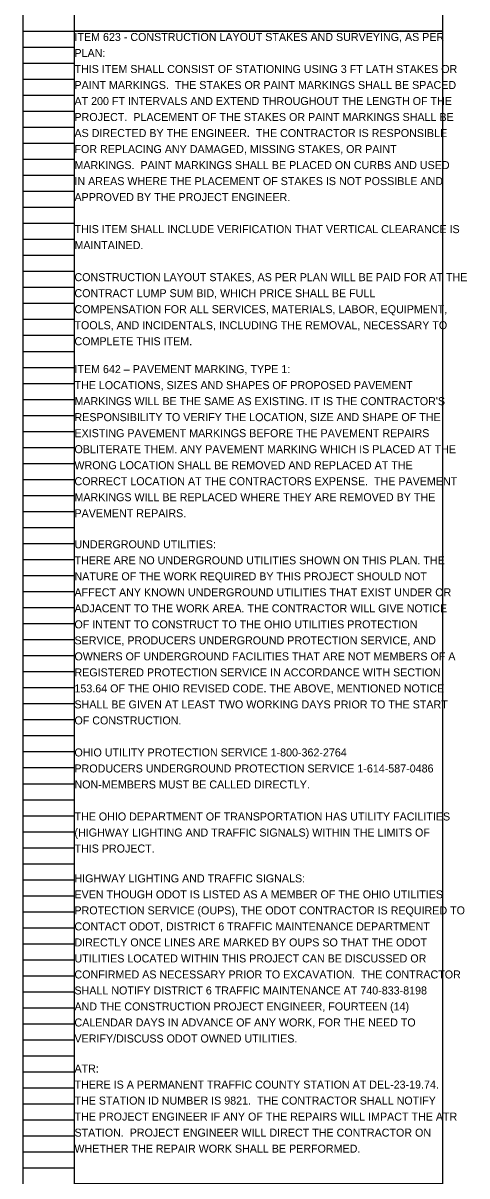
# Model space of a CAD drawing. Extents: x 16463 to 16495, y 5662 to 5823.
# Drawn here: x 16463.05 to 16470.82, y 5763.13 to 5783.29 of the extents above; entities that cross this region are included whole.
import ezdxf

# ---------------------------------------------------------------- set-up
doc = ezdxf.new("R2010")
doc.units = 0
for name, color, linetype in [('Default', 7, 'Continuous'), ('SC_Scratch1', 7, 'Continuous'), ('SH_Data', 7, 'Continuous')]:
    doc.layers.add(name, color=color, linetype=linetype)

msp = doc.modelspace()

# ---------------------------------------------------------------- linework, layer by layer
at = {"layer": 'SC_Scratch1'}
for points in [[(16463.949, 5803.312), (16470.389, 5803.312), (16470.389, 5783.152), (16463.949, 5783.152)], [(16463.949, 5783.152), (16470.389, 5783.152), (16470.389, 5762.992), (16463.949, 5762.992)]]:
    msp.add_lwpolyline(points, close=True, dxfattribs=at)
at = {"layer": 'SH_Data'}
for p, q in [((16463.049, 5783.152), (16463.049, 5803.312)), ((16463.949, 5783.152), (16463.949, 5803.312)), ((16463.049, 5762.992), (16463.049, 5783.152)), ((16463.049, 5783.152), (16463.949, 5783.152)), ((16463.049, 5783.152), (16463.949, 5783.152)), ((16463.949, 5762.992), (16463.949, 5783.152)), ((16463.049, 5782.872), (16463.949, 5782.872)), ((16463.049, 5782.592), (16463.949, 5782.592)), ((16463.049, 5782.312), (16463.949, 5782.312)), ((16463.049, 5782.032), (16463.949, 5782.032)), ((16463.049, 5781.752), (16463.949, 5781.752)), ((16463.049, 5781.472), (16463.949, 5781.472)), ((16463.049, 5781.192), (16463.949, 5781.192)), ((16463.049, 5780.912), (16463.949, 5780.912)), ((16463.049, 5780.632), (16463.949, 5780.632)), ((16463.049, 5780.352), (16463.949, 5780.352)), ((16463.049, 5780.072), (16463.949, 5780.072)), ((16463.049, 5779.792), (16463.949, 5779.792)), ((16463.049, 5779.512), (16463.949, 5779.512)), ((16463.049, 5779.232), (16463.949, 5779.232)), ((16463.049, 5778.952), (16463.949, 5778.952)), ((16463.049, 5778.672), (16463.949, 5778.672)), ((16463.049, 5778.392), (16463.949, 5778.392)), ((16463.049, 5778.112), (16463.949, 5778.112)), ((16463.049, 5777.832), (16463.949, 5777.832)), ((16463.049, 5777.552), (16463.949, 5777.552)), ((16463.049, 5777.272), (16463.949, 5777.272)), ((16463.049, 5776.992), (16463.949, 5776.992)), ((16463.049, 5776.712), (16463.949, 5776.712)), ((16463.049, 5776.432), (16463.949, 5776.432)), ((16463.049, 5776.152), (16463.949, 5776.152)), ((16463.049, 5775.872), (16463.949, 5775.872)), ((16463.049, 5775.592), (16463.949, 5775.592)), ((16463.049, 5775.312), (16463.949, 5775.312)), ((16463.049, 5775.032), (16463.949, 5775.032)), ((16463.049, 5774.752), (16463.949, 5774.752)), ((16463.049, 5774.472), (16463.949, 5774.472)), ((16463.049, 5774.192), (16463.949, 5774.192)), ((16463.049, 5773.912), (16463.949, 5773.912)), ((16463.049, 5773.632), (16463.949, 5773.632)), ((16463.049, 5773.352), (16463.949, 5773.352)), ((16463.049, 5773.072), (16463.949, 5773.072)), ((16463.049, 5772.792), (16463.949, 5772.792)), ((16463.049, 5772.512), (16463.949, 5772.512)), ((16463.049, 5772.232), (16463.949, 5772.232)), ((16463.049, 5771.952), (16463.949, 5771.952)), ((16463.049, 5771.672), (16463.949, 5771.672)), ((16463.049, 5771.392), (16463.949, 5771.392)), ((16463.049, 5771.112), (16463.949, 5771.112)), ((16463.049, 5770.832), (16463.949, 5770.832)), ((16463.049, 5770.552), (16463.949, 5770.552)), ((16463.049, 5770.272), (16463.949, 5770.272)), ((16463.049, 5769.992), (16463.949, 5769.992)), ((16463.049, 5769.712), (16463.949, 5769.712)), ((16463.049, 5769.432), (16463.949, 5769.432)), ((16463.049, 5769.152), (16463.949, 5769.152)), ((16463.049, 5768.872), (16463.949, 5768.872)), ((16463.049, 5768.592), (16463.949, 5768.592)), ((16463.049, 5768.312), (16463.949, 5768.312)), ((16463.049, 5768.032), (16463.949, 5768.032)), ((16463.049, 5767.752), (16463.949, 5767.752)), ((16463.049, 5767.472), (16463.949, 5767.472)), ((16463.049, 5767.192), (16463.949, 5767.192)), ((16463.049, 5766.912), (16463.949, 5766.912)), ((16463.049, 5766.632), (16463.949, 5766.632)), ((16463.049, 5766.352), (16463.949, 5766.352)), ((16463.049, 5766.072), (16463.949, 5766.072)), ((16463.049, 5765.792), (16463.949, 5765.792)), ((16463.049, 5765.512), (16463.949, 5765.512)), ((16463.049, 5765.232), (16463.949, 5765.232)), ((16463.049, 5764.952), (16463.949, 5764.952)), ((16463.049, 5764.672), (16463.949, 5764.672)), ((16463.049, 5764.392), (16463.949, 5764.392)), ((16463.049, 5764.112), (16463.949, 5764.112)), ((16463.049, 5763.832), (16463.949, 5763.832)), ((16463.049, 5763.552), (16463.949, 5763.552)), ((16463.049, 5763.272), (16463.949, 5763.272))]:
    msp.add_line(p, q, dxfattribs=at)

# ---------------------------------------------------------------- texts
at = {"layer": 'Default'}
for s, p in [('ITEM 623 - CONSTRUCTION LAYOUT STAKES AND SURVEYING, AS PER ', (16463.949, 5782.979)), ('PLAN:', (16463.949, 5782.699)), ('THIS ITEM SHALL CONSIST OF STATIONING USING 3 FT LATH STAKES OR ', (16463.949, 5782.419)), ('PAINT MARKINGS.  THE STAKES OR PAINT MARKINGS SHALL BE SPACED ', (16463.949, 5782.139)), ('AT 200 FT INTERVALS AND EXTEND THROUGHOUT THE LENGTH OF THE ', (16463.949, 5781.859)), ('PROJECT.  PLACEMENT OF THE STAKES OR PAINT MARKINGS SHALL BE ', (16463.949, 5781.579)), ('AS DIRECTED BY THE ENGINEER.  THE CONTRACTOR IS RESPONSIBLE ', (16463.949, 5781.299)), ('FOR REPLACING ANY DAMAGED, MISSING STAKES, OR PAINT ', (16463.949, 5781.019)), ('MARKINGS.  PAINT MARKINGS SHALL BE PLACED ON CURBS AND USED ', (16463.949, 5780.739)), ('IN AREAS WHERE THE PLACEMENT OF STAKES IS NOT POSSIBLE AND ', (16463.949, 5780.459)), ('APPROVED BY THE PROJECT ENGINEER.', (16463.949, 5780.179)), ('THIS ITEM SHALL INCLUDE VERIFICATION THAT VERTICAL CLEARANCE IS ', (16463.949, 5779.619)), ('MAINTAINED.', (16463.949, 5779.339)), ('CONSTRUCTION LAYOUT STAKES, AS PER PLAN WILL BE PAID FOR AT THE ', (16463.949, 5778.779)), ('CONTRACT LUMP SUM BID, WHICH PRICE SHALL BE FULL ', (16463.949, 5778.499)), ('COMPENSATION FOR ALL SERVICES, MATERIALS, LABOR, EQUIPMENT, ', (16463.949, 5778.219)), ('TOOLS, AND INCIDENTALS, INCLUDING THE REMOVAL, NECESSARY TO ', (16463.949, 5777.939)), ('COMPLETE THIS ITEM.', (16463.949, 5777.659)), ('ITEM 642 – PAVEMENT MARKING, TYPE 1:', (16463.949, 5777.171)), ('THE LOCATIONS, SIZES AND SHAPES OF PROPOSED PAVEMENT ', (16463.949, 5776.891)), ("MARKINGS WILL BE THE SAME AS EXISTING. IT IS THE CONTRACTOR'S ", (16463.949, 5776.611)), ('RESPONSIBILITY TO VERIFY THE LOCATION, SIZE AND SHAPE OF THE ', (16463.949, 5776.331)), ('EXISTING PAVEMENT MARKINGS BEFORE THE PAVEMENT REPAIRS ', (16463.949, 5776.051)), ('OBLITERATE THEM. ANY PAVEMENT MARKING WHICH IS PLACED AT THE ', (16463.949, 5775.771)), ('WRONG LOCATION SHALL BE REMOVED AND REPLACED AT THE ', (16463.949, 5775.491)), ('CORRECT LOCATION AT THE CONTRACTORS EXPENSE.  THE PAVEMENT ', (16463.949, 5775.211)), ('MARKINGS WILL BE REPLACED WHERE THEY ARE REMOVED BY THE ', (16463.949, 5774.931)), ('PAVEMENT REPAIRS.', (16463.949, 5774.651)), ('UNDERGROUND UTILITIES:', (16463.949, 5774.108)), ('THERE ARE NO UNDERGROUND UTILITIES SHOWN ON THIS PLAN. THE ', (16463.949, 5773.828)), ('NATURE OF THE WORK REQUIRED BY THIS PROJECT SHOULD NOT ', (16463.949, 5773.548)), ('AFFECT ANY KNOWN UNDERGROUND UTILITIES THAT EXIST UNDER OR ', (16463.949, 5773.268)), ('ADJACENT TO THE WORK AREA. THE CONTRACTOR WILL GIVE NOTICE ', (16463.949, 5772.988)), ('OF INTENT TO CONSTRUCT TO THE OHIO UTILITIES PROTECTION ', (16463.949, 5772.708)), ('SERVICE, PRODUCERS UNDERGROUND PROTECTION SERVICE, AND ', (16463.949, 5772.428)), ('OWNERS OF UNDERGROUND FACILITIES THAT ARE NOT MEMBERS OF A ', (16463.949, 5772.148)), ('REGISTERED PROTECTION SERVICE IN ACCORDANCE WITH SECTION ', (16463.949, 5771.868)), ('153.64 OF THE OHIO REVISED CODE. THE ABOVE, MENTIONED NOTICE ', (16463.949, 5771.588)), ('SHALL BE GIVEN AT LEAST TWO WORKING DAYS PRIOR TO THE START ', (16463.949, 5771.308)), ('OF CONSTRUCTION.', (16463.949, 5771.028)), ('OHIO UTILITY PROTECTION SERVICE 1-800-362-2764', (16463.949, 5770.468)), ('PRODUCERS UNDERGROUND PROTECTION SERVICE 1-614-587-0486', (16463.949, 5770.188)), ('NON-MEMBERS MUST BE CALLED DIRECTLY.', (16463.949, 5769.908)), ('THE OHIO DEPARTMENT OF TRANSPORTATION HAS UTILITY FACILITIES ', (16463.949, 5769.348)), ('(HIGHWAY LIGHTING AND TRAFFIC SIGNALS) WITHIN THE LIMITS OF ', (16463.949, 5769.068)), ('THIS PROJECT.', (16463.949, 5768.788)), ('HIGHWAY LIGHTING AND TRAFFIC SIGNALS:', (16463.949, 5768.266)), ('EVEN THOUGH ODOT IS LISTED AS A MEMBER OF THE OHIO UTILITIES ', (16463.949, 5767.986)), ('PROTECTION SERVICE (OUPS), THE ODOT CONTRACTOR IS REQUIRED TO ', (16463.949, 5767.706)), ('CONTACT ODOT, DISTRICT 6 TRAFFIC MAINTENANCE DEPARTMENT ', (16463.949, 5767.426)), ('DIRECTLY ONCE LINES ARE MARKED BY OUPS SO THAT THE ODOT ', (16463.949, 5767.146)), ('UTILITIES LOCATED WITHIN THIS PROJECT CAN BE DISCUSSED OR ', (16463.949, 5766.866)), ('CONFIRMED AS NECESSARY PRIOR TO EXCAVATION.  THE CONTRACTOR ', (16463.949, 5766.586)), ('SHALL NOTIFY DISTRICT 6 TRAFFIC MAINTENANCE AT 740-833-8198 ', (16463.949, 5766.306)), ('AND THE CONSTRUCTION PROJECT ENGINEER, FOURTEEN (14) ', (16463.949, 5766.026)), ('CALENDAR DAYS IN ADVANCE OF ANY WORK, FOR THE NEED TO ', (16463.949, 5765.746)), ('VERIFY/DISCUSS ODOT OWNED UTILITIES.', (16463.949, 5765.466)), ('ATR:', (16463.949, 5764.94)), ('THERE IS A PERMANENT TRAFFIC COUNTY STATION AT DEL-23-19.74.  ', (16463.949, 5764.66)), ('THE STATION ID NUMBER IS 9821.  THE CONTRACTOR SHALL NOTIFY ', (16463.949, 5764.38)), ('THE PROJECT ENGINEER IF ANY OF THE REPAIRS WILL IMPACT THE ATR ', (16463.949, 5764.1)), ('STATION.  PROJECT ENGINEER WILL DIRECT THE CONTRACTOR ON ', (16463.949, 5763.82)), ('WHETHER THE REPAIR WORK SHALL BE PERFORMED.', (16463.949, 5763.54))]:
    msp.add_text(s, height=0.14, dxfattribs=at).set_placement(p)

doc.saveas('drawing.dxf')
